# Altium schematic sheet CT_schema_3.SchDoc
size 176 x 147 mm
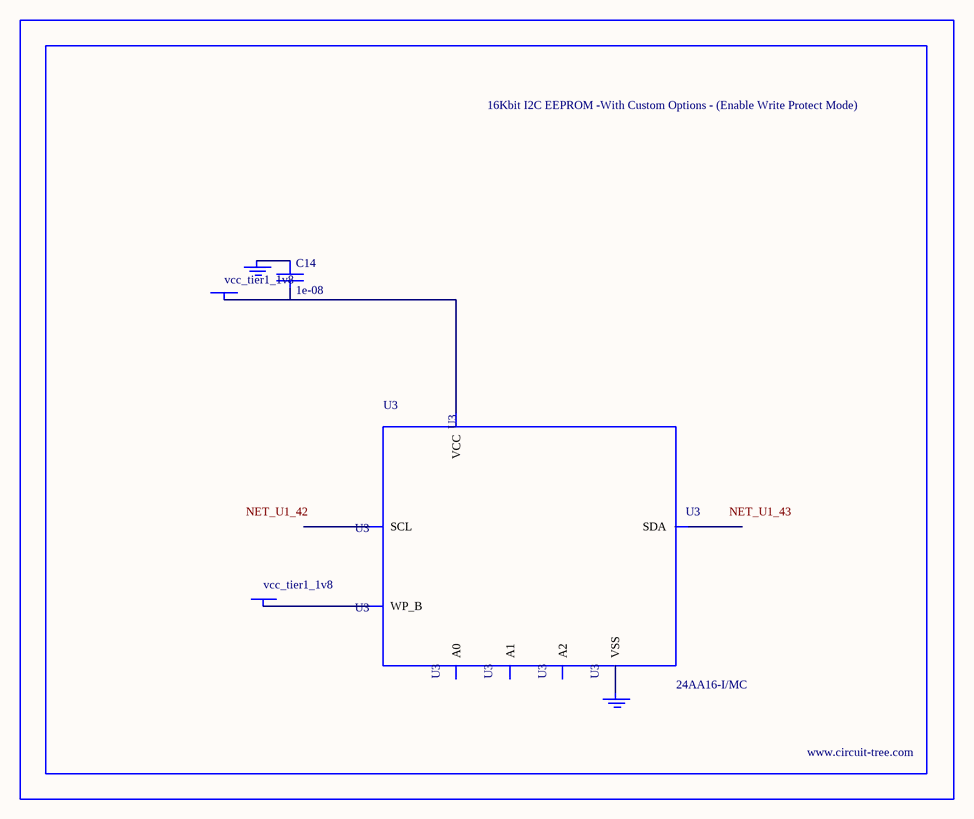
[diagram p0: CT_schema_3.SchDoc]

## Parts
BORDER2  (no value)
C14  1e-08  [C0402]
GND_INSTANCE_2_0  (no value)
GND_INSTANCE_2_1  (no value)
POWER_INSTANCE_2_0  vcc_tier1_1v8
POWER_INSTANCE_2_1  vcc_tier1_1v8
U3  24AA16-I/MC  [TDFN-8/6MM]

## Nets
NetC14_1: C14.1 GND_INSTANCE_2_0.0(GND)
NetC14_2: C14.2 POWER_INSTANCE_2_1.0(PWR) U3.8(VCC)
NetGND_INSTANCE_2_1_0: GND_INSTANCE_2_1.0(GND) U3.4(VSS)
NetPOWER_INSTANCE_2_0_0: POWER_INSTANCE_2_0.0(PWR) U3.7(WP_B)

Not connected (* = marked no-connect by the designer): U3 1(A0) 2(A1) 3(A2) 5(SDA) 6(SCL)

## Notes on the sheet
- Labels drawn without touching a wire or pin: NET_U1_42, NET_U1_43

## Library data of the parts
BORDER2 = BORDER_PAGE2
C14 = C0402C103K3RAC
GND_INSTANCE_2_0 GND_INSTANCE_2_1 = GND
POWER_INSTANCE_2_0 POWER_INSTANCE_2_1 = PWR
